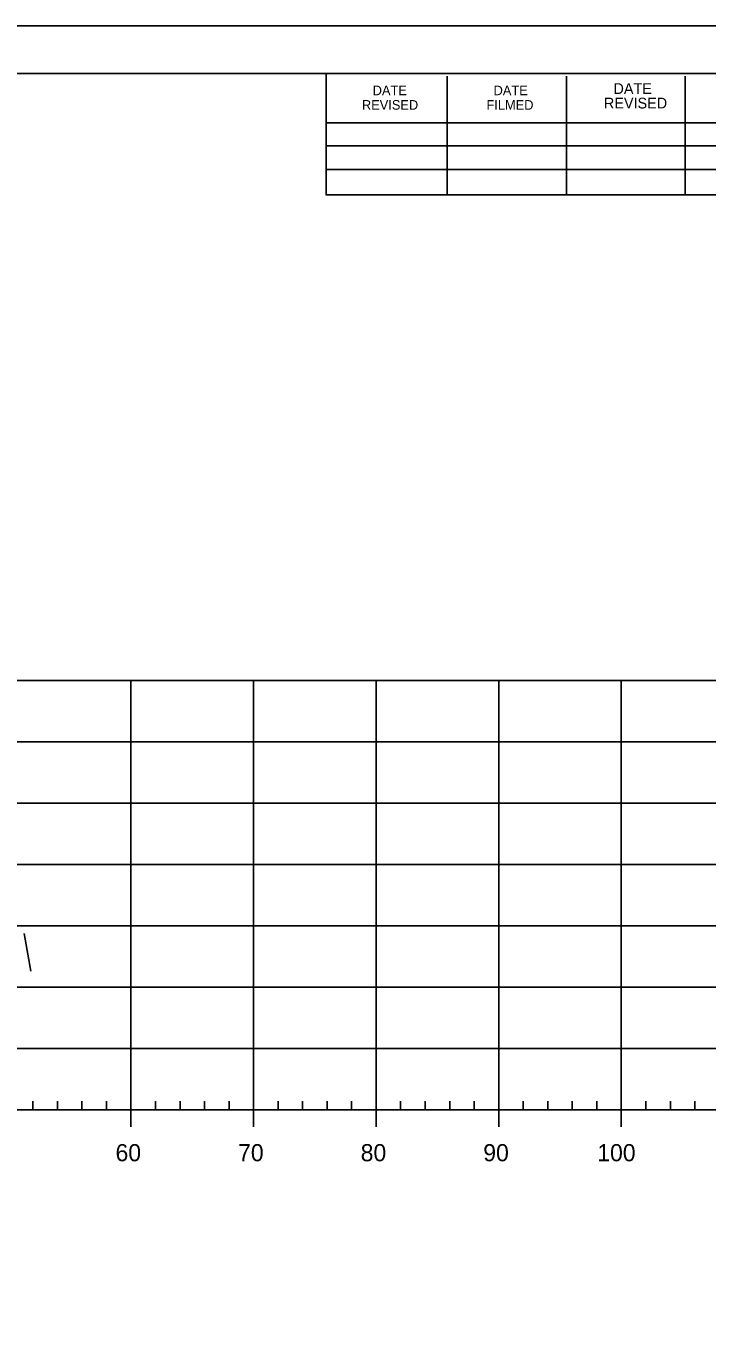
# Model space of a CAD drawing. Extents: x 1359801 to 1362404, y 372415 to 374228.
# Drawn here: x 1360022.8 to 1360078.4, y 373482.5 to 373588 of the extents above; entities that cross this region are included whole.
import ezdxf

# ---------------------------------------------------------------- set-up
doc = ezdxf.new("R2010")
doc.units = 0
for name, color, linetype in [('S_DRG_PT_SYM', 7, 'Continuous'), ('S_MAILBOX', 7, 'Continuous'), ('S_PRIMARY_CTL', 7, 'Continuous'), ('S_SHOULDER', 7, 'Continuous'), ('S_UTL_PT_SYM', 7, 'Continuous'), ('S_WATER_UTILITIES', 7, 'Continuous')]:
    doc.layers.add(name, color=color, linetype=linetype)

msp = doc.modelspace()

# ---------------------------------------------------------------- linework, layer by layer
at = {"layer": 'S_DRG_PT_SYM'}
msp.add_lwpolyline([(1360022.64, 373513.97), (1360023.19, 373510.89)], dxfattribs=at)
at = {"layer": 'S_MAILBOX'}
for p, q in [((1359826.35, 373534.6), (1360116.35, 373534.6)), ((1359826.35, 373534.6), (1360116.35, 373534.6)), ((1360031.35, 373499.6), (1360031.35, 373534.6)), ((1360031.35, 373499.6), (1360031.35, 373534.6)), ((1360041.35, 373499.6), (1360041.35, 373534.6)), ((1360041.35, 373499.6), (1360041.35, 373534.6)), ((1360051.35, 373499.6), (1360051.35, 373534.6)), ((1360051.35, 373499.6), (1360051.35, 373534.6)), ((1360061.35, 373499.6), (1360061.35, 373534.6)), ((1360061.35, 373499.6), (1360061.35, 373534.6)), ((1360071.35, 373499.6), (1360071.35, 373534.6)), ((1360071.35, 373499.6), (1360071.35, 373534.6)), ((1359826.35, 373529.6), (1360116.35, 373529.6)), ((1359826.35, 373529.6), (1360116.35, 373529.6)), ((1359826.35, 373524.6), (1360116.35, 373524.6)), ((1359826.35, 373524.6), (1360116.35, 373524.6)), ((1359826.35, 373519.6), (1360116.35, 373519.6)), ((1359826.35, 373519.6), (1360116.35, 373519.6)), ((1359826.35, 373514.6), (1360116.35, 373514.6)), ((1359826.35, 373514.6), (1360116.35, 373514.6)), ((1359826.35, 373509.6), (1360116.35, 373509.6)), ((1359826.35, 373509.6), (1360116.35, 373509.6)), ((1359826.35, 373504.6), (1360116.35, 373504.6)), ((1359826.35, 373504.6), (1360116.35, 373504.6)), ((1359826.35, 373499.6), (1360116.35, 373499.6)), ((1359826.35, 373499.6), (1360116.35, 373499.6))]:
    msp.add_line(p, q, dxfattribs=at)
at = {"layer": 'S_SHOULDER'}
msp.add_line((1359800.95, 373587.95), (1360134.28, 373587.95), dxfattribs=at)
for points in [[(1359800.94, 373587.95), (1360134.28, 373587.95), (1360134.28, 373374.61), (1359800.94, 373374.61)], [(1360047.27, 373584.06), (1360047.27, 373574.18), (1360083, 373574.18), (1360083, 373571.26), (1360106.2, 373571.26), (1360106.2, 373546.93), (1360129.53, 373546.93), (1360129.53, 373378.6), (1359813.35, 373378.6), (1359813.35, 373584.06)]]:
    msp.add_lwpolyline(points, close=True, dxfattribs=at)
at = {"layer": 'S_UTL_PT_SYM'}
for p, q in [((1359813.35, 373584.06), (1360129.53, 373584.06)), ((1360047.27, 373574.18), (1360047.27, 373584.06)), ((1360057.13, 373574.18), (1360057.13, 373583.86)), ((1360066.89, 373574.18), (1360066.89, 373583.86)), ((1360076.57, 373574.18), (1360076.57, 373583.86)), ((1360047.27, 373580.04), (1360086.43, 373580.04)), ((1360047.27, 373578.18), (1360086.43, 373578.18)), ((1360047.27, 373574.18), (1360047.27, 373576.24)), ((1360047.27, 373576.24), (1360086.43, 373576.24)), ((1360129.53, 373574.18), (1360047.27, 373574.18))]:
    msp.add_line(p, q, dxfattribs=at)
at = {"layer": 'S_WATER_UTILITIES'}
for p, q in [((1360023.35, 373499.6), (1360023.35, 373500.3)), ((1360025.35, 373499.6), (1360025.35, 373500.3)), ((1360027.35, 373499.6), (1360027.35, 373500.3)), ((1360029.35, 373499.6), (1360029.35, 373500.3)), ((1360033.35, 373499.6), (1360033.35, 373500.3)), ((1360035.35, 373499.6), (1360035.35, 373500.3)), ((1360037.35, 373499.6), (1360037.35, 373500.3)), ((1360039.35, 373499.6), (1360039.35, 373500.3)), ((1360043.35, 373499.6), (1360043.35, 373500.3)), ((1360045.35, 373499.6), (1360045.35, 373500.3)), ((1360047.35, 373499.6), (1360047.35, 373500.3)), ((1360049.35, 373499.6), (1360049.35, 373500.3)), ((1360053.35, 373499.6), (1360053.35, 373500.3)), ((1360055.35, 373499.6), (1360055.35, 373500.3)), ((1360057.35, 373499.6), (1360057.35, 373500.3)), ((1360059.35, 373499.6), (1360059.35, 373500.3)), ((1360063.35, 373499.6), (1360063.35, 373500.3)), ((1360065.35, 373499.6), (1360065.35, 373500.3)), ((1360067.35, 373499.6), (1360067.35, 373500.3)), ((1360069.35, 373499.6), (1360069.35, 373500.3)), ((1360073.35, 373499.6), (1360073.35, 373500.3)), ((1360075.35, 373499.6), (1360075.35, 373500.3)), ((1360077.35, 373499.6), (1360077.35, 373500.3)), ((1359826.35, 373499.6), (1360116.35, 373499.6)), ((1360031.35, 373498.2), (1360031.35, 373499.6)), ((1360041.35, 373498.2), (1360041.35, 373499.6)), ((1360051.35, 373498.2), (1360051.35, 373499.6)), ((1360061.35, 373498.2), (1360061.35, 373499.6)), ((1360071.35, 373498.2), (1360071.35, 373499.6))]:
    msp.add_line(p, q, dxfattribs=at)

# ---------------------------------------------------------------- texts
at = {"layer": 'S_PRIMARY_CTL'}
for s, p in [('60', (1360030.09, 373495.4)), ('70', (1360040.09, 373495.4)), ('80', (1360050.09, 373495.4)), ('90', (1360060.09, 373495.4)), ('100', (1360069.39, 373495.4))]:
    msp.add_text(s, height=1.4, dxfattribs=at).set_placement(p)
at = {"layer": 'S_UTL_PT_SYM'}
for s, height, p in [('DATE', 0.782, (1360051.07, 373582.3)), ('DATE', 0.782, (1360060.93, 373582.3)), ('DATE', 0.879, (1360070.71, 373582.4)), ('REVISED', 0.782, (1360050.19, 373581.12)), ('FILMED', 0.782, (1360060.35, 373581.12)), ('REVISED', 0.879, (1360069.93, 373581.22))]:
    msp.add_text(s, height=height, rotation=360, dxfattribs=at).set_placement(p)

doc.saveas('drawing.dxf')
